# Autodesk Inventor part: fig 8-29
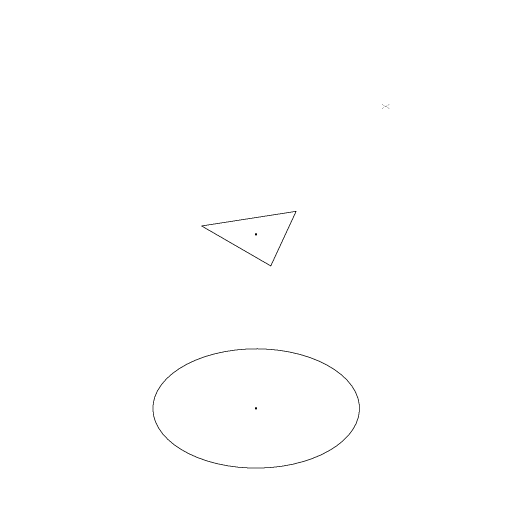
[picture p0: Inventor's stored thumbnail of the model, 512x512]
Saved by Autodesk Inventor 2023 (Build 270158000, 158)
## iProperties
Created: 2001-12
Part Number: fig 8-29
Document SubType Name: Modeling
Designer: CADSoft
Density: 1 g/cm^3
Material: Generic
Appearance: Default
Control State: 0
Master: False
Checked Out: False
Shininess: 77.0
Angle Display Precision: 2
Document Length Units: 11269
Document Angle Units: 11279
Document Time Units: 11290
Document Mass Units: 11283
Document Length Units Precision: 3
Document Angle Units Precision: 2
Density: 0.0
Volumn: 0.0
Area: 0.0
PropertySet Name: Model Information
Author: CADSoft
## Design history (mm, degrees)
workplane "Work Plane3"
workplane "Work Plane4"
sketch "Sketch12"
  geometry: L1 (0, 10.598)-(9.178, -5.299); L2 (9.178, -5.299)-(-9.178, -5.299); L3 (-9.178, -5.299)-(0, 10.598); 1 further point
  constraints: 6 end point, 5 other
workplane "Work Plane5"
body "Solid1"
sketch "Sketch1"
  geometry: C1 r 19.387 at (0, 0); 1 further point
  constraints: 1 centre point, 1 coincident, 1 other
sketch "Sketch2"
  geometry: 1 further point
